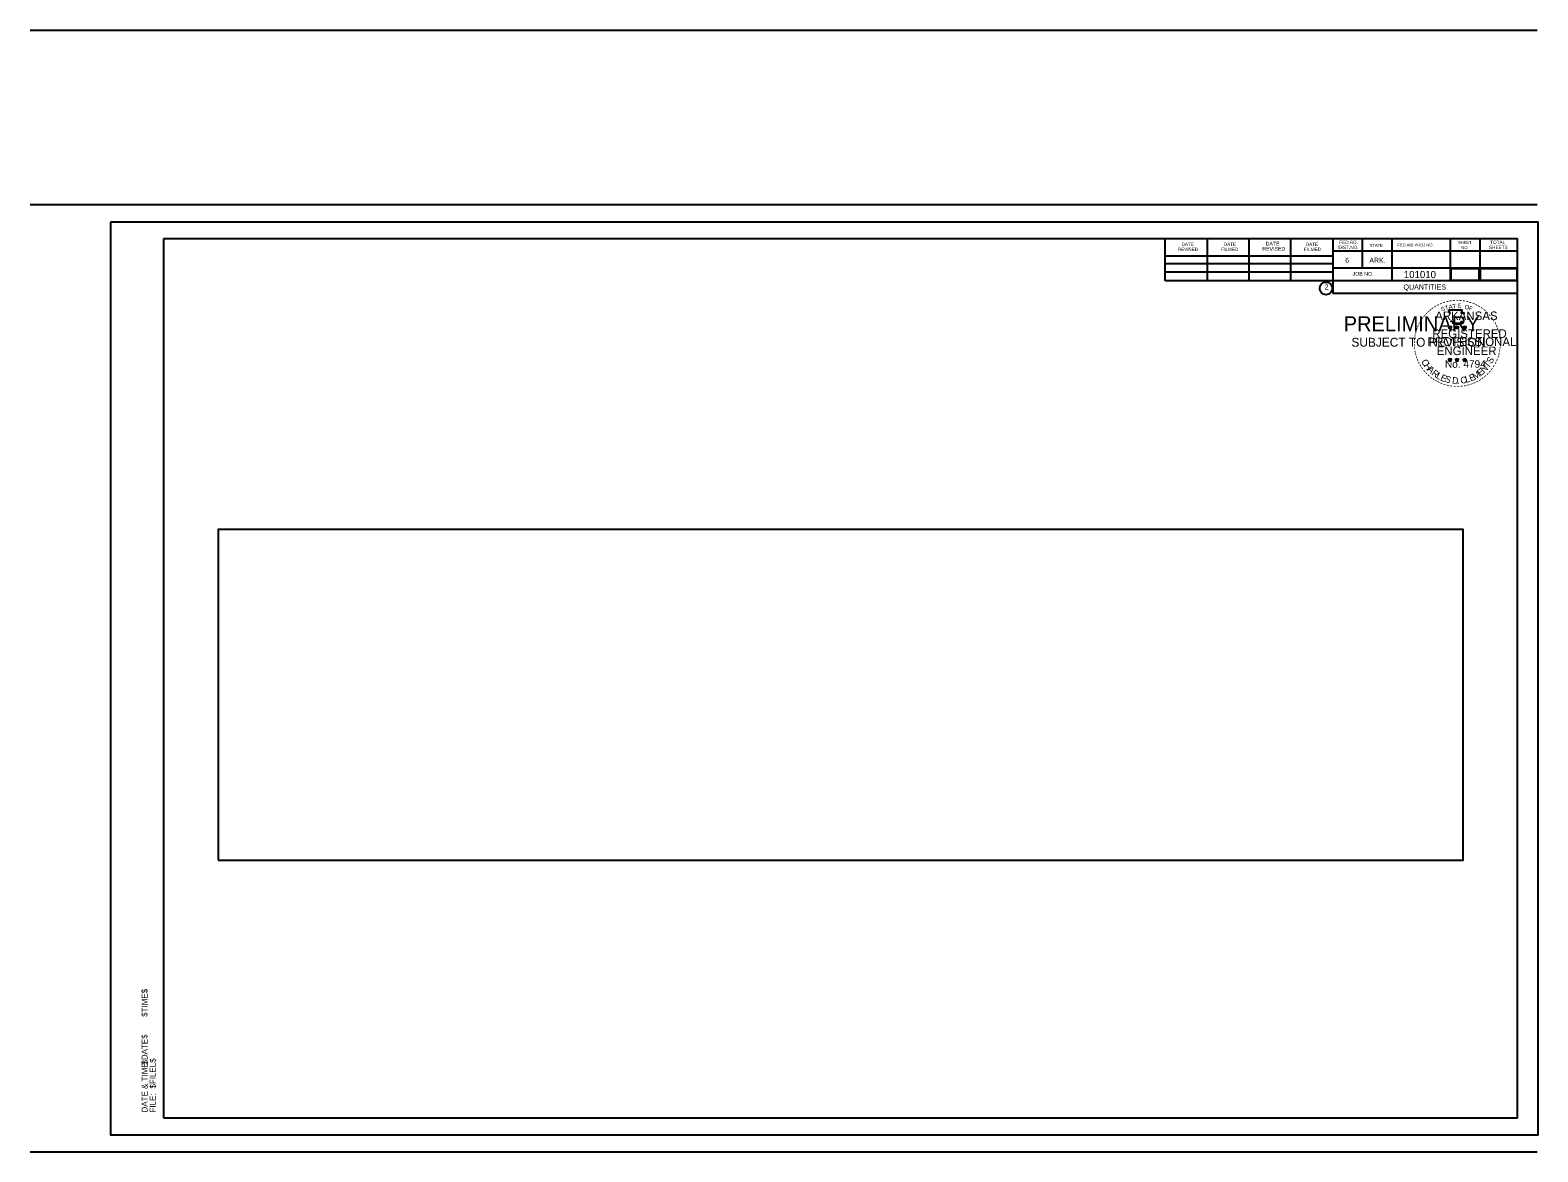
# Model space of a CAD drawing. Extents: x 9844 to 18514, y 8651 to 12569.
# Drawn here: x 9844 to 11605, y 8651 to 9961 of the extents above; entities that cross this region are included whole.
import ezdxf

# ---------------------------------------------------------------- set-up
doc = ezdxf.new("R2010")
doc.units = 0
for name, color, linetype in [('Default', 7, 'Continuous'), ('Quantities', 7, 'Continuous'), ('R_Border Notes', 7, 'Continuous'), ('R_No Plot', 7, 'Continuous'), ('STAMP_PE_CRAFTON-SIGNATURE', 7, 'Continuous'), ('STAMP_PE_SEAL-INFO', 7, 'Continuous'), ('STAMP_PE_TXT', 7, 'Continuous'), ('STAMP_PRELIMINARY', 7, 'Continuous'), ('Total_Pages', 7, 'Continuous')]:
    doc.layers.add(name, color=color, linetype=linetype)

msp = doc.modelspace()

# ---------------------------------------------------------------- linework, layer by layer
at = {"layer": 'Quantities'}
msp.add_lwpolyline([(10063.4, 8991.1), (11517.5, 8991.1), (11517.5, 9377.5), (10063.4, 9377.5)], close=True, dxfattribs=at)
at = {"layer": 'R_No Plot'}
msp.add_lwpolyline([(11502.9, 9668.6), (11536.2, 9668.6), (11536.2, 9681.8), (11502.9, 9681.8)], close=True, dxfattribs=at)
at = {"layer": 'STAMP_PE_SEAL-INFO'}
msp.add_lwpolyline([(9938, 9736.8), (11604.7, 9736.8), (11604.7, 8670.1), (9938, 8670.1)], close=True, dxfattribs=at)
msp.add_lwpolyline([(9938, 9736.8), (11604.7, 9736.8), (11604.7, 8670.1), (9938, 8670.1)], close=True, dxfattribs=at)
at = {"layer": 'STAMP_PE_TXT'}
for p, q in [((11500.3, 9614), (11502.1, 9613.5)), ((11500.3, 9614), (11501.6, 9613.8)), ((11500.3, 9614), (11501.5, 9613.4)), ((11502.1, 9615.3), (11501.8, 9614)), ((11502.1, 9613.5), (11502.1, 9615.3)), ((11502.1, 9615.3), (11502.3, 9614.1)), ((11503.8, 9614), (11502.1, 9613.5)), ((11503.8, 9614), (11502.4, 9613.8)), ((11503.8, 9614), (11502.8, 9613.5)), ((11508.7, 9614), (11510.4, 9613.5)), ((11508.7, 9614), (11509.9, 9613.8)), ((11508.7, 9614), (11509.8, 9613.4)), ((11510.4, 9615.3), (11510.2, 9614)), ((11510.4, 9613.5), (11510.4, 9615.3)), ((11510.4, 9615.3), (11510.6, 9614.1)), ((11512.1, 9614), (11510.4, 9613.5)), ((11512.1, 9614), (11510.7, 9613.8)), ((11512.1, 9614), (11511.1, 9613.5)), ((11517.5, 9614), (11519.2, 9613.4)), ((11517.5, 9614), (11518.7, 9613.7)), ((11517.5, 9614), (11518.7, 9613.4)), ((11519.2, 9615.2), (11519, 9614)), ((11519.2, 9613.4), (11519.2, 9615.2)), ((11519.2, 9615.2), (11519.5, 9614)), ((11521, 9614), (11519.2, 9613.4)), ((11521, 9614), (11519.5, 9613.7)), ((11521, 9614), (11519.9, 9613.5)), ((11501, 9612), (11502.1, 9613.5)), ((11501, 9612), (11501.6, 9613.2)), ((11501, 9612), (11502, 9613.1)), ((11503.1, 9612), (11502, 9613.1)), ((11503.1, 9612), (11502.1, 9613.5)), ((11503.1, 9612), (11502.4, 9613.4)), ((11509.3, 9612), (11510.4, 9613.5)), ((11509.3, 9612), (11510, 9613.2)), ((11509.3, 9612), (11510.4, 9613.1)), ((11511.5, 9612), (11510.4, 9613.5)), ((11511.5, 9612), (11510.4, 9613.1)), ((11511.5, 9612), (11510.8, 9613.4)), ((11518.1, 9611.9), (11519.2, 9613.4)), ((11518.1, 9611.9), (11518.8, 9613.2)), ((11518.1, 9611.9), (11519.2, 9613)), ((11520.3, 9611.9), (11519.2, 9613.4)), ((11520.3, 9611.9), (11519.2, 9613)), ((11520.3, 9611.9), (11519.6, 9613.4)), ((11500.3, 9576.2), (11502, 9575.6)), ((11500.3, 9576.2), (11501.6, 9575.9)), ((11500.3, 9576.2), (11501.5, 9575.6)), ((11501, 9574.1), (11502, 9575.6)), ((11501, 9574.1), (11501.6, 9575.3)), ((11501, 9574.1), (11502, 9575.2)), ((11502, 9577.4), (11501.8, 9576.2)), ((11502, 9575.6), (11502, 9577.4)), ((11502, 9577.4), (11502.3, 9576.2)), ((11503.8, 9576.2), (11502, 9575.6)), ((11503.1, 9574.1), (11502, 9575.6)), ((11503.1, 9574.1), (11502, 9575.2)), ((11503.8, 9576.2), (11502.3, 9575.9)), ((11503.1, 9574.1), (11502.4, 9575.6)), ((11503.8, 9576.2), (11502.7, 9575.7)), ((11508.6, 9576.2), (11510.4, 9575.6)), ((11508.6, 9576.2), (11509.9, 9575.9)), ((11508.6, 9576.2), (11509.8, 9575.6)), ((11509.3, 9574.1), (11510.4, 9575.6)), ((11509.3, 9574.1), (11509.9, 9575.3)), ((11509.3, 9574.1), (11510.4, 9575.2)), ((11510.4, 9577.4), (11510.2, 9576.2)), ((11510.4, 9575.6), (11510.4, 9577.4)), ((11510.4, 9577.4), (11510.6, 9576.2)), ((11512.1, 9576.2), (11510.4, 9575.6)), ((11511.4, 9574.1), (11510.4, 9575.6)), ((11511.4, 9574.1), (11510.4, 9575.2)), ((11512.1, 9576.2), (11510.7, 9575.9)), ((11511.4, 9574.1), (11510.8, 9575.6)), ((11512.1, 9576.2), (11511.1, 9575.7)), ((11517.5, 9576.1), (11519.2, 9575.6)), ((11517.5, 9576.1), (11518.7, 9575.9)), ((11517.5, 9576.1), (11518.7, 9575.5)), ((11518.1, 9574.1), (11519.2, 9575.6)), ((11518.1, 9574.1), (11518.8, 9575.3)), ((11518.1, 9574.1), (11519.2, 9575.2)), ((11519.2, 9577.4), (11519, 9576.1)), ((11519.2, 9575.6), (11519.2, 9577.4)), ((11519.2, 9577.4), (11519.5, 9576.1)), ((11520.9, 9576.1), (11519.2, 9575.6)), ((11520.3, 9574.1), (11519.2, 9575.6)), ((11520.3, 9574.1), (11519.2, 9575.1)), ((11520.9, 9576.1), (11519.5, 9575.9)), ((11520.3, 9574.1), (11519.6, 9575.5)), ((11520.9, 9576.1), (11519.9, 9575.6))]:
    msp.add_line(p, q, dxfattribs=at)
for points in [[(11500.5, 9633.4), (11501.9, 9629.3)], [(11518.1, 9628.8), (11518.8, 9630.2), (11515.4, 9630.1), (11516.1, 9633.4), (11500.5, 9633.4)], [(11502.1, 9615.3), (11503.1, 9612), (11500.3, 9614), (11503.8, 9614), (11501, 9612), (11502.1, 9615.3)], [(11503, 9621.3), (11503, 9620.9), (11505.8, 9620.8), (11505.5, 9618.4), (11514.9, 9618.4), (11515.9, 9621.1)], [(11510.4, 9615.3), (11511.5, 9612), (11508.7, 9614), (11512.1, 9614), (11509.3, 9612), (11510.4, 9615.3)], [(11519.2, 9615.2), (11520.3, 9611.9), (11517.5, 9614), (11521, 9614), (11518.1, 9611.9), (11519.2, 9615.2)], [(11502, 9577.4), (11503.1, 9574.1), (11500.3, 9576.2), (11503.8, 9576.2), (11501, 9574.1), (11502, 9577.4)], [(11510.4, 9577.4), (11511.4, 9574.1), (11508.6, 9576.2), (11512.1, 9576.2), (11509.3, 9574.1), (11510.4, 9577.4)], [(11519.2, 9577.4), (11520.3, 9574.1), (11517.5, 9576.1), (11520.9, 9576.1), (11518.1, 9574.1), (11519.2, 9577.4)]]:
    msp.add_lwpolyline(points, dxfattribs=at)
for centre, radius in [((11502, 9613.5), 0.861), ((11502, 9613.5), 0.723), ((11502, 9613.5), 0.579), ((11502, 9613.5), 0.495), ((11502, 9613.5), 0.374), ((11510.4, 9613.5), 0.861), ((11510.4, 9613.5), 0.723), ((11510.4, 9613.5), 0.579), ((11510.4, 9613.5), 0.495), ((11510.4, 9613.5), 0.374), ((11519.2, 9613.4), 0.861), ((11519.2, 9613.4), 0.723), ((11519.2, 9613.4), 0.579), ((11519.2, 9613.4), 0.495), ((11519.2, 9613.4), 0.374), ((11502, 9613.5), 0.248), ((11502, 9613.5), 0.148), ((11510.4, 9613.5), 0.248), ((11510.4, 9613.5), 0.148), ((11519.2, 9613.4), 0.248), ((11519.2, 9613.4), 0.148), ((11502, 9575.6), 0.861), ((11502, 9575.6), 0.723), ((11502, 9575.6), 0.579), ((11502, 9575.6), 0.495), ((11502, 9575.6), 0.374), ((11502, 9575.6), 0.248), ((11502, 9575.6), 0.148), ((11510.4, 9575.6), 0.861), ((11510.4, 9575.6), 0.723), ((11510.4, 9575.6), 0.579), ((11510.4, 9575.6), 0.495), ((11510.4, 9575.6), 0.374), ((11510.4, 9575.6), 0.248), ((11510.4, 9575.6), 0.148), ((11519.2, 9575.6), 0.861), ((11519.2, 9575.6), 0.723), ((11519.2, 9575.6), 0.579), ((11519.2, 9575.6), 0.495), ((11519.2, 9575.6), 0.374), ((11519.2, 9575.6), 0.248), ((11519.2, 9575.6), 0.148)]:
    msp.add_circle(centre, radius, dxfattribs=at)
at = {"layer": 'STAMP_PRELIMINARY'}
for p, q in [((9843.9, 9960.6), (11603.9, 9960.6)), ((11603.9, 9756.7), (9843.9, 9756.7)), ((10000, 9717.3), (11580.9, 9717.3)), ((10000, 8690), (10000, 9717.3)), ((10762.6, 9716), (10762.6, 9716)), ((10762.6, 9716), (10762.6, 9716)), ((11169.6, 9667.9), (11169.6, 9717.3)), ((11218.9, 9667.9), (11218.9, 9716.3)), ((11267.7, 9667.9), (11267.7, 9716.3)), ((11316.1, 9667.9), (11316.1, 9716.3)), ((11365.4, 9717.3), (11365.4, 9653.3)), ((11580.9, 9702.6), (11365.4, 9702.6)), ((11399.6, 9717.3), (11399.6, 9682.6)), ((11434.3, 9717.3), (11434.3, 9667.9)), ((11502.2, 9717.3), (11502.2, 9667.9)), ((11536.9, 9717.3), (11536.9, 9667.9)), ((11580.9, 8690), (11580.9, 9717.3)), ((11580.9, 9702.7), (11580.9, 9702.7)), ((11169.6, 9697.2), (11365.4, 9697.2)), ((11169.6, 9687.9), (11365.4, 9687.9)), ((11169.6, 9678.2), (11365.4, 9678.2)), ((11580.9, 9667.9), (11169.6, 9667.9)), ((11580.9, 9682.6), (11365.4, 9682.6)), ((11365.4, 9653.3), (11580.9, 9653.3)), ((11580.9, 8690), (10000, 8690)), ((9843.9, 8650.6), (11603.9, 8650.6))]:
    msp.add_line(p, q, dxfattribs=at)
msp.add_circle((11357.3, 9659), 7.33, dxfattribs=at)
at = {"layer": 'Total_Pages'}
msp.add_lwpolyline([(11537.4, 9668.6), (11580.4, 9668.6), (11580.4, 9681.8), (11537.4, 9681.8)], close=True, dxfattribs=at)

# ---------------------------------------------------------------- texts
at = {"layer": 'Default'}
for s, height, p in [('$TIME$', 6.98, (9981, 8808.3)), ('$DATE$', 6.98, (9981, 8752.5)), ('DATE & TIME:', 6.984, (9981, 8696.6)), ('$FILEL$', 6.98, (9990.6, 8724.5)), ('FILE: ', 6.98, (9990.6, 8696.6))]:
    msp.add_text(s, height=height, rotation=90, dxfattribs=at).set_placement(p)
at = {"layer": 'R_Border Notes'}
for s, height, p in [('101010', 8.4, (11448.2, 9671)), ('QUANTITIES', 6, (11447.7, 9657.6))]:
    msp.add_text(s, height=height, dxfattribs=at).set_placement(p)
at = {"layer": 'STAMP_PE_CRAFTON-SIGNATURE'}
for s, height, p in [('PRELIMINARY', 17.5, (11377.9, 9609)), ('SUBJECT TO REVISION', 10.376, (11387, 9590.9))]:
    msp.add_text(s, height=height, dxfattribs=at).set_placement(p)
at = {"layer": 'STAMP_PE_TXT'}
for s, height, rotation, p in [('-', 8, 42.9622, (11477.5, 9628.3)), ('-', 8, 38.9507, (11479.7, 9630.4)), ('-', 8, 36.2317, (11482, 9632.3)), ('-', 8, 34.0636, (11484.9, 9634.3)), ('-', 8, 28.7918, (11487.9, 9636.1)), ('-', 8, 24.3072, (11491.1, 9637.7)), ('S', 5, 21.594, (11492.3, 9631.8)), ('-', 8, 19.1761, (11494.3, 9639.1)), ('T', 5, 16.4036, (11496.9, 9633.5)), ('-', 8, 13.6302, (11498, 9640.3)), ('A', 5, 11.2132, (11501, 9634.7)), ('-', 8, 10.2193, (11501.4, 9641.1)), ('T', 5, 6.0228, (11505.2, 9635.6)), ('-', 8, 5.8968, (11505, 9641.6)), ('-', 8, 0.1862, (11508.9, 9642)), ('E', 5, 0.8323, (11510.8, 9636.1)), ('-', 8, 357.743, (11512.5, 9641.9)), ('-', 8, 352.1617, (11516.2, 9641.6)), ('O', 5, 350.4515, (11518.8, 9635.1)), ('-', 8, 347.2049, (11519.8, 9641.1)), ('F', 5, 340.0707, (11523.5, 9633.9)), ('-', 8, 342.3362, (11523, 9640.3)), ('-', 8, 337.8551, (11526.7, 9639.2)), ('-', 8, 334.1211, (11529.8, 9637.8)), ('-', 8, 329.6409, (11532.7, 9636.4)), ('-', 8, 325.8627, (11535.9, 9634.6)), ('-', 8, 320.5297, (11539, 9632.5)), ('-', 8, 315.5786, (11542, 9630)), ('-', 8, 67.7743, (11466.7, 9611.9)), ('-', 8, 62.8713, (11468, 9615)), ('-', 8, 58.0706, (11469.6, 9618)), ('-', 8, 54.2325, (11471.2, 9620.7)), ('-', 8, 50.6142, (11473.2, 9623.5)), ('-', 8, 48.4231, (11475.3, 9625.9)), ('-', 8, 309.8797, (11544.8, 9627.3)), ('-', 8, 306.6522, (11547.5, 9624.3)), ('-', 7, 303.6753, (11549.9, 9621.4)), ('-', 8, 299.6684, (11551.5, 9618.4)), ('-', 8, 294.6628, (11553.1, 9615.3)), ('-', 8, 89.0622, (11463.4, 9594.7)), ('-', 8, 85.1863, (11463.6, 9598.2)), ('-', 8, 81.2013, (11464, 9601.6)), ('-', 8, 75.461, (11464.6, 9605.2)), ('-', 8, 72.3945, (11465.6, 9608.8)), ('-', 8, 290.5728, (11554.4, 9612.5)), ('-', 8, 285.1233, (11555.6, 9609.6)), ('-', 8, 280.5493, (11556.6, 9605.8)), ('-', 8, 276.5962, (11557.4, 9602)), ('-', 8, 274.3301, (11557.7, 9598.4)), ('-', 8, 94.1959, (11463.6, 9591)), ('-', 8, 98.9479, (11464, 9587.7)), ('-', 8, 101.7149, (11464.7, 9584)), ('-', 8, 105.4578, (11465.5, 9581.1)), ('-', 8, 109.0874, (11466.5, 9577.9)), ('S', 7.7, 57.878, (11550.5, 9570.3)), ('-', 8, 255.7626, (11555.9, 9581.8)), ('-', 8, 255.7626, (11556.8, 9585.2)), ('-', 8, 260.9953, (11557.4, 9588.6)), ('-', 8, 263.5172, (11557.7, 9591.9)), ('-', 8, 269.9407, (11557.8, 9595.2)), ('-', 8, 114.0643, (11467.8, 9574.9)), ('-', 8, 115.7289, (11469.3, 9571.8)), ('-', 8, 120.4471, (11471.1, 9568.9)), ('-', 8, 125.8934, (11473.1, 9566.1)), ('C', 7.7, 296.9133, (11468.2, 9573.9)), ('-', 8, 130.7181, (11475.4, 9563.3)), ('H', 7.7, 303.2799, (11471.1, 9568.7)), ('-', 8, 134.2238, (11478, 9560.6)), ('A', 7.7, 316.013, (11474.8, 9563.6)), ('R', 7.7, 322.3796, (11479.9, 9558.7)), ('L', 7.7, 328.7461, (11485, 9554.9)), ('M', 7.7, 32.4117, (11531.2, 9552.1)), ('E', 7.7, 38.7783, (11537.6, 9556.2)), ('N', 7.7, 45.1449, (11542, 9559.9)), ('T', 7.7, 51.5114, (11546.8, 9565.1)), ('-', 8, 231.2538, (11547.4, 9565.3)), ('-', 8, 233.8452, (11549.5, 9568.1)), ('-', 8, 239.0712, (11551.5, 9571.4)), ('-', 8, 244.6197, (11553.5, 9575.1)), ('-', 8, 247.8887, (11554.8, 9578.3)), ('-', 8, 138.9338, (11480.7, 9558.3)), ('-', 8, 144.6463, (11483.4, 9556.3)), ('-', 8, 148.0898, (11486.2, 9554.4)), ('-', 8, 151.5704, (11489.1, 9552.8)), ('-', 8, 154.6002, (11491.7, 9551.6)), ('-', 8, 158.5612, (11494.9, 9550.3)), ('E', 7.7, 335.1127, (11490.1, 9552.1)), ('-', 8, 162.7983, (11498.3, 9549.2)), ('S', 7.7, 341.4792, (11495.4, 9550)), ('-', 8, 167.5555, (11501.9, 9548.4)), ('-', 8, 173.1155, (11505.7, 9547.9)), ('D', 7.7, 354.2124, (11504.2, 9547.9)), ('-', 8, 176.5183, (11509.5, 9547.6)), ('-', 8, 181.5918, (11513.2, 9547.7)), ('.', 7.7, 0.5789, (11510.1, 9547.5)), ('-', 8, 185.8167, (11517.2, 9548.1)), ('C', 7.7, 6.9455, (11514.7, 9547.7)), ('-', 8, 191.2858, (11520.9, 9548.7)), ('L', 7.7, 13.3121, (11520.6, 9548.7)), ('-', 8, 195.4743, (11524.6, 9549.7)), ('E', 7.7, 19.6786, (11526.1, 9550.3)), ('-', 8, 200.7184, (11528, 9550.9)), ('-', 8, 204.2516, (11531, 9552.3)), ('-', 8, 207.3568, (11534.2, 9553.9)), ('-', 8, 212.2491, (11537, 9555.6)), ('-', 8, 215.7363, (11539.6, 9557.6)), ('-', 8, 221.0851, (11542.4, 9559.9)), ('-', 8, 225.7653, (11545, 9562.5))]:
    msp.add_text(s, height=height, rotation=rotation, dxfattribs=at).set_placement(p)
for s, height, p in [('ARKANSAS', 10, (11484.8, 9622)), ('PROFESSIONAL', 10, (11475.6, 9591.7)), ('REGISTERED', 10, (11481.4, 9601.2)), ('ENGINEER', 10, (11486.6, 9581.1)), ('No. 4794', 8.78, (11496.2, 9566.3))]:
    msp.add_text(s, height=height, dxfattribs=at).set_placement(p)
at = {"layer": 'STAMP_PRELIMINARY'}
for s, height, p in [('REVISED', 3.91, (11184.2, 9702.6)), ('DATE', 3.91, (11188.6, 9708.5)), ('FILMED', 3.91, (11235, 9702.6)), ('DATE', 3.91, (11237.9, 9708.5)), ('REVISED', 4.4, (11282.9, 9703.1)), ('DATE', 4.4, (11286.8, 9709)), ('FILMED', 3.91, (11331.7, 9702.6)), ('DATE', 3.91, (11333.7, 9708.5)), ('DIST.NO.', 3.91, (11371.8, 9705)), ('FED.RD.', 3.91, (11372.8, 9710.9)), ('STATE', 3.42, (11408.4, 9707.5)), ('FED.AID PROJ.NO.', 3.42, (11440.7, 9708)), ('SHEET', 3.42, (11511.5, 9710.9)), ('NO.', 3.42, (11515.4, 9705)), ('SHEETS', 3.91, (11547.7, 9705)), ('TOTAL', 3.91, (11549.1, 9710.9)), ('6', 5.86, (11379.6, 9688.9)), ('ARK.', 5.86, (11407.9, 9688.9)), ('JOB NO.', 4.4, (11388.4, 9673.8)), ('2', 5.86, (11355.7, 9657.7))]:
    msp.add_text(s, height=height, dxfattribs=at).set_placement(p)

doc.saveas('drawing.dxf')
